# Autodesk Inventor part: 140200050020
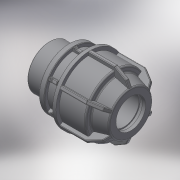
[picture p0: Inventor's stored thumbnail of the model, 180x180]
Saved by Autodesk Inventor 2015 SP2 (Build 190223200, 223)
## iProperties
Created: 2017-08
Part Number: 140200050020
Material: Generic
Description: PLASSON L.14 MALE ADAPTOR (SILVER) 50-2''
Document SubType Name: Modeling
Designer: KIM
Density: 1 g/cm^3
Appearance: Default
Author: KIM
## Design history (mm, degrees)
derived "140200.ipt"
feature "Solid1::140200.ipt"
tag "TaggingFeature1"
body "Solid1"
other parameters: "d4" = 15 deg, "d5" = 59.4, "d6" = 19.602, "d10" = 92, "d16" = 51, "d17" = 4.5, "d19" = 7.8, "d21" = 7.8, "d22" = 71.5368, "d24" = 4.5, "d25" = 82.8, "d26" = 69, "d27" = 4.5, "d28" = 135 deg, "d29" = 2.7, "d31" = 2.5, "d44" = 1, "d45" = 1.5, "d46" = 150 deg, "d49" = 4.6, "d50" = 0, "d51" = 0.92, "d52" = 1.84, "d53" = 45 deg, "d54" = 21, "d55" = 6.3, "d56" = 4.6, "d57" = 0, "d58" = 1.5, "d59" = 1, "d61" = 360 deg, "d63" = 59.614, "d65" = 26, "d66" = 80.4789, "R_" = 59.614, "E_" = 92, "l_2" = 26
